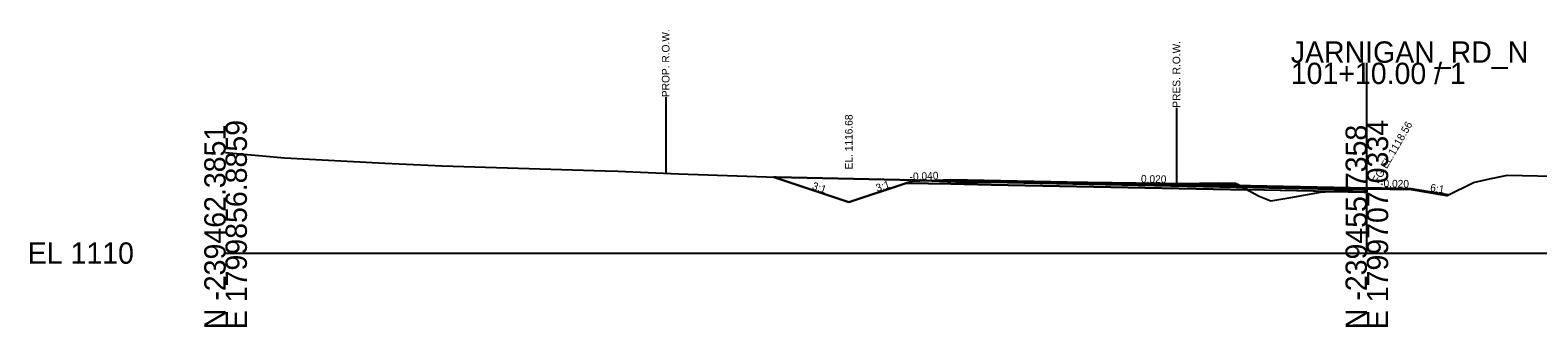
# Model space of a CAD drawing. Extents: x 214513 to 217151, y 214739 to 216780.
# Drawn here: x 215422.7 to 215620.8, y 215238.7 to 215277.6 of the extents above; entities that cross this region are included whole.
import ezdxf

# ---------------------------------------------------------------- set-up
doc = ezdxf.new("R2010")
doc.units = 0
for name, color, linetype in [('CONCEPT - TRANSPORTATION - Roads Text', 7, 'Continuous'), ('DESIGN - CENTERLINE - Proposed', 7, 'Continuous'), ('DESIGN - CENTERLINE - Proposed Text', 7, 'Continuous'), ('DESIGN - DRAINAGE - Special Ditches', 7, 'Continuous'), ('DESIGN - EARTHWORK - Shapes', 7, 'Continuous'), ('DESIGN - ROW - Right-of-Way Linework', 7, 'Continuous'), ('DESIGN - TRANSPORTATION - Text', 7, 'Continuous'), ('DESIGN - TYPICAL - Slope Tie Text', 7, 'Continuous'), ('Section', 7, 'Continuous'), ('SURVEY - DTM GRAPHICS - Triangles', 7, 'Continuous'), ('SURVEY - PROPERTY - ROW Lines', 7, 'Continuous'), ('XSCell', 7, 'Continuous')]:
    doc.layers.add(name, color=color, linetype=linetype)

msp = doc.modelspace()

# ---------------------------------------------------------------- linework, layer by layer
at = {"layer": 'DESIGN - DRAINAGE - Special Ditches'}
for points in [[(215530.27, 215255.04), (215520.4, 215258.33)], [(215538.58, 215257.81), (215530.27, 215255.04)], [(215543.69, 215258.02), (215543.69, 215257.77), (215548.98, 215257.66), (215598.36, 215256.67), (215598.36, 215256.34), (215548.98, 215257.33), (215543.69, 215257.44), (215537.81, 215257.56), (215538.58, 215257.81), (215543.69, 215258.02)], [(215543.69, 215258.02), (215598.36, 215256.92), (215598.36, 215256.82), (215543.69, 215257.92), (215543.69, 215257.92), (215543.69, 215258.02), (215543.69, 215258.02)], [(215543.69, 215257.92), (215598.36, 215256.82), (215598.36, 215256.67), (215598.36, 215256.67), (215543.69, 215257.77), (215543.69, 215257.77), (215543.69, 215257.92), (215543.69, 215257.92), (215543.69, 215257.92)], [(215604.18, 215256.81), (215598.36, 215256.92), (215598.36, 215256.82), (215604.18, 215256.71), (215604.18, 215256.71), (215604.18, 215256.81), (215604.18, 215256.81)], [(215604.18, 215256.81), (215609.04, 215256)]]:
    msp.add_lwpolyline(points, dxfattribs=at)
at = {"layer": 'DESIGN - EARTHWORK - Shapes'}
for p, q in [((215520.4, 215258.33), (215530.27, 215255.04)), ((215530.27, 215255.04), (215537.81, 215257.56)), ((215537.81, 215257.56), (215538.58, 215257.81)), ((215538.58, 215257.81), (215537.81, 215257.56)), ((215538.58, 215257.81), (215540.53, 215257.89)), ((215540.53, 215257.89), (215538.58, 215257.81)), ((215556.12, 215257.67), (215549.26, 215257.66)), ((215582.03, 215257), (215549.26, 215257.66)), ((215549.26, 215257.66), (215582.03, 215257)), ((215581.75, 215257.16), (215556.12, 215257.67)), ((215556.12, 215257.67), (215581.75, 215257.16)), ((215568.04, 215257.53), (215581.56, 215257.26)), ((215581.56, 215257.26), (215568.04, 215257.53)), ((215581.75, 215257.16), (215581.56, 215257.26)), ((215582.03, 215257), (215581.75, 215257.16)), ((215582.66, 215256.66), (215582.03, 215257)), ((215593.43, 215256.44), (215582.66, 215256.66)), ((215593.43, 215256.44), (215598.36, 215256.34)), ((215598.36, 215256.76), (215597.3, 215256.7)), ((215597.3, 215256.7), (215598.36, 215256.67)), ((215598.36, 215256.82), (215598.36, 215256.76)), ((215603.56, 215256.72), (215598.36, 215256.82)), ((215598.36, 215256.67), (215598.36, 215256.76)), ((215604.18, 215256.81), (215604.18, 215256.71)), ((215609.04, 215256), (215604.18, 215256.81))]:
    msp.add_line(p, q, dxfattribs=at)
for points in [[(215540.53, 215257.89), (215539, 215257.95), (215520.71, 215258.32), (215520.4, 215258.33)], [(215537.81, 215257.56), (215543.69, 215257.44), (215548.98, 215257.33), (215582.66, 215256.66)], [(215549.26, 215257.66), (215546.42, 215257.65), (215540.53, 215257.89)], [(215568.04, 215257.53), (215558.55, 215257.67), (215556.12, 215257.67)], [(215581.56, 215257.26), (215581.1, 215257.51), (215578.87, 215257.54), (215573.83, 215257.44), (215573.33, 215257.45), (215568.04, 215257.53)], [(215582.66, 215256.66), (215584.21, 215255.82), (215585.73, 215255.2), (215588.36, 215255.65), (215592.27, 215256.37), (215593.43, 215256.44)], [(215597.3, 215256.7), (215597.14, 215256.69), (215593.43, 215256.44)], [(215598.36, 215256.34), (215598.36, 215256.67), (215597.3, 215256.7)], [(215598.36, 215256.76), (215598.66, 215256.78), (215599.18, 215256.78), (215603.56, 215256.72)], [(215604.18, 215256.71), (215608.84, 215255.93), (215608.89, 215255.93), (215608.93, 215255.94), (215609.04, 215256)]]:
    msp.add_lwpolyline(points, dxfattribs=at)
at = {"layer": 'DESIGN - ROW - Right-of-Way Linework'}
msp.add_lwpolyline([(215506.2, 215268.84), (215506.2, 215258.84)], dxfattribs=at)
at = {"layer": 'SURVEY - DTM GRAPHICS - Triangles'}
msp.add_lwpolyline([(215448.36, 215261.59), (215456.11, 215260.85), (215469.28, 215260.17), (215476.83, 215259.8), (215498.23, 215259.16), (215499.93, 215259.1), (215507.89, 215258.77), (215520.71, 215258.32), (215539, 215257.95), (215546.42, 215257.65), (215558.55, 215257.67), (215573.83, 215257.44), (215578.87, 215257.54), (215581.1, 215257.51), (215584.21, 215255.82), (215585.73, 215255.2), (215588.36, 215255.65), (215592.27, 215256.37), (215597.14, 215256.69), (215598.66, 215256.78), (215599.18, 215256.78), (215604.18, 215256.71), (215608.84, 215255.93), (215608.89, 215255.93), (215608.93, 215255.94), (215612.36, 215257.64), (215614.47, 215258.12), (215616.86, 215258.6), (215624.76, 215258.41)], dxfattribs=at)
at = {"layer": 'SURVEY - PROPERTY - ROW Lines'}
msp.add_lwpolyline([(215573.33, 215267.45), (215573.33, 215257.45)], dxfattribs=at)
at = {"layer": 'XSCell'}
for p, q in [((215598.36, 215248.36), (215598.36, 215273.36)), ((215448.36, 215248.36), (215598.36, 215248.36)), ((215598.36, 215248.36), (215748.36, 215248.36))]:
    msp.add_line(p, q, dxfattribs=at)

# ---------------------------------------------------------------- texts
at = {"layer": 'CONCEPT - TRANSPORTATION - Roads Text'}
for s, rotation, p in [('-0.040', 2.2906, (215538.28, 215257.9)), ('0.020', 358.8542, (215568.66, 215257.62)), ('-0.020', 358.8542, (215600.1, 215257.02))]:
    msp.add_text(s, height=1, rotation=rotation, dxfattribs=at).set_placement(p)
at = {"layer": 'DESIGN - CENTERLINE - Proposed'}
msp.add_text('EL. 1116.68', height=1, rotation=90, dxfattribs=at).set_placement((215530.77, 215259.35))
at = {"layer": 'DESIGN - CENTERLINE - Proposed Text'}
msp.add_text('FG EL.1118.56', height=1, rotation=60, dxfattribs=at).set_placement((215599.86, 215257.42))
at = {"layer": 'DESIGN - TRANSPORTATION - Text'}
for s, p in [('PROP. R.O.W.', (215506.7, 215268.84)), ('PRES. R.O.W.', (215573.83, 215267.45))]:
    msp.add_text(s, height=1, rotation=90, dxfattribs=at).set_placement(p)
at = {"layer": 'DESIGN - TYPICAL - Slope Tie Text'}
for s, rotation, p in [('3:1', 341.5651, (215525.36, 215256.78)), ('3:1', 18.4349, (215534.01, 215256.39)), ('6:1', 350.5377, (215606.63, 215256.5))]:
    msp.add_text(s, height=1, rotation=rotation, dxfattribs=at).set_placement(p)
at = {"layer": 'Section'}
msp.add_text('-', height=0.0001, dxfattribs=at).set_placement((215448.36, 215248.36))
at = {"layer": 'XSCell'}
for s, p in [('JARNIGAN_RD_N', (215588.36, 215273.36)), ('101+10.00 / 1', (215588.36, 215270.56)), ('EL 1110', (215422.36, 215246.96))]:
    msp.add_text(s, height=2.8, dxfattribs=at).set_placement(p)
for s, p in [('E 1799856.8859', (215451.16, 215238.36)), ('E 1799707.0334', (215601.16, 215238.36)), ('N -239462.3851', (215448.36, 215238.36)), ('N -239455.7358', (215598.36, 215238.36))]:
    msp.add_text(s, height=2.8, rotation=90, dxfattribs=at).set_placement(p)

doc.saveas('drawing.dxf')
